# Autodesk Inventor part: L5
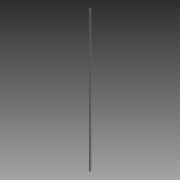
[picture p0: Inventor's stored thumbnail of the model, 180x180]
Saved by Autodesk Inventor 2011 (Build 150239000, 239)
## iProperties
Created: 2014-02
Part Number: L5
Document SubType Name: Modeling
Designer: Evgeny
Density: 1 g/cm^3
Author: Evgeny
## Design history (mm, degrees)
sketch "Эскиз1"
  geometry: C1 r 4 at (0, 0); 1 further point
  constraints: 1 centre point, 1 coincident
  dimensions: "d0" = 8 diameter of C1
extrude "Выдавливание1" new body sketch "Эскиз1" distance "d1" = 668; taper "d2" = 0 deg
feature "Оболочка1" dims "d3" = 1
node "Твердое тело1"
